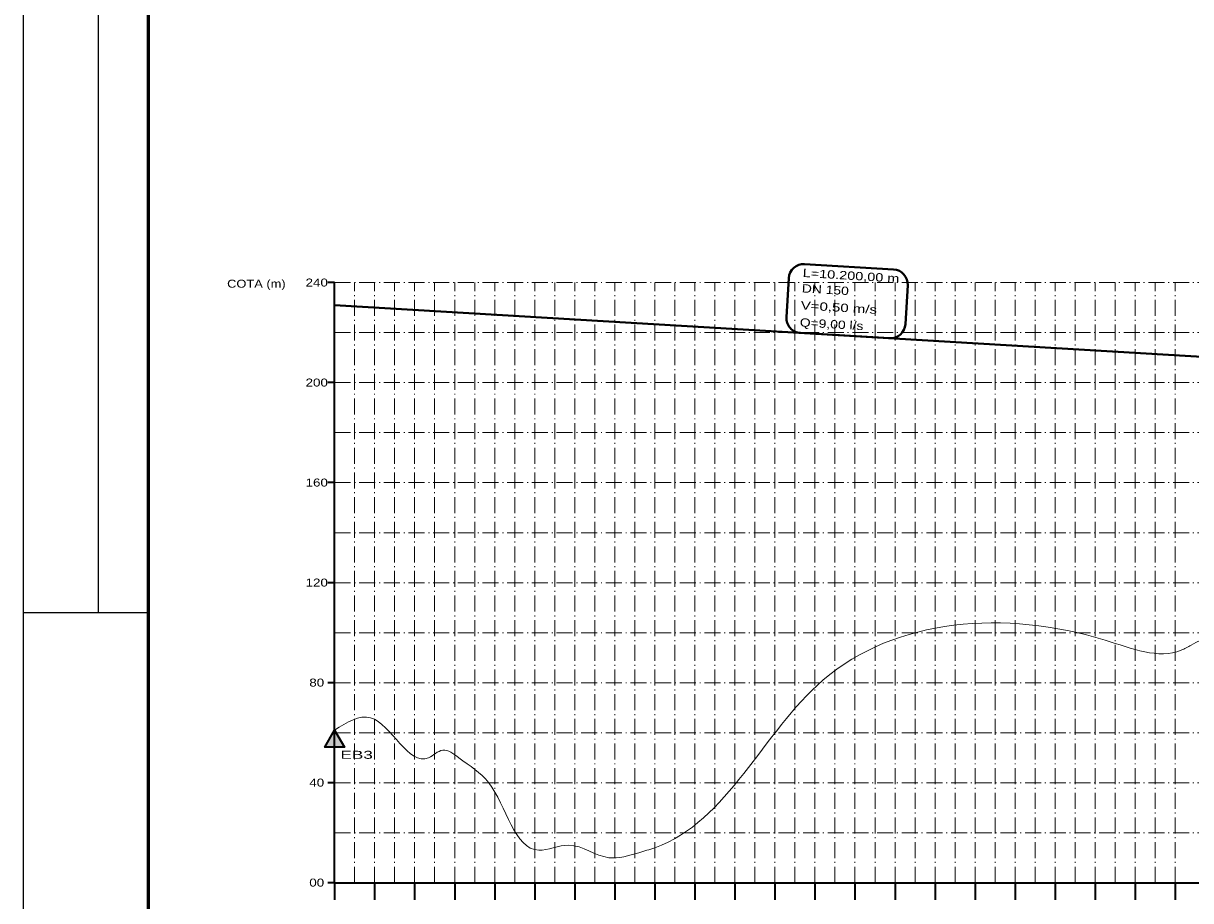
# Model space of a CAD drawing. Extents: x -4 to 42046, y -3 to 29697.
# Drawn here: x -4 to 11660, y 11967 to 20739 of the extents above; entities that cross this region are included whole.
import ezdxf
from ezdxf.enums import TextEntityAlignment as Align

# ---------------------------------------------------------------- set-up
doc = ezdxf.new("R2010")
doc.units = 0
doc.header["$LTSCALE"] = 32
doc.linetypes.add('DOT_DASHED', pattern=[7.7, 5, -1.2, 0.3, -1.2])
for name, color, linetype, lineweight in [('1', 7, 'DOT_DASHED', 13), ('24', 7, 'Continuous', 35), ('55', 7, 'Continuous', 13), ('62', 7, 'Continuous', 13), ('63', 7, 'Continuous', 25), ('9', 7, 'Continuous', 40)]:
    doc.layers.add(name, color=color, linetype=linetype, lineweight=lineweight)

msp = doc.modelspace()

# ---------------------------------------------------------------- hatches: boundary and pattern name
at = {"layer": '62'}
msp.add_hatch(color=256, dxfattribs=at).paths.add_polyline_path([(3105.77, 13671.17), (3204.42, 13502.71), (3009.21, 13501.5)])

# ---------------------------------------------------------------- linework, layer by layer
at = {"layer": '1'}
for p, q in [((3105.77, 18146.17), (22505.77, 18146.17)), ((3305.77, 12146.17), (3305.77, 18146.17)), ((3505.77, 12146.17), (3505.77, 18146.17)), ((3705.77, 12146.17), (3705.77, 18146.17)), ((3905.77, 12146.17), (3905.77, 18146.17)), ((4105.77, 12146.17), (4105.77, 18146.17)), ((4305.77, 12146.17), (4305.77, 18146.17)), ((4505.77, 12146.17), (4505.77, 18146.17)), ((4705.77, 12146.17), (4705.77, 18146.17)), ((4905.77, 12146.17), (4905.77, 18146.17)), ((5105.77, 12146.17), (5105.77, 18146.17)), ((5305.77, 12146.17), (5305.77, 18146.17)), ((5505.77, 12146.17), (5505.77, 18146.17)), ((5705.77, 12146.17), (5705.77, 18146.17)), ((5905.77, 12146.17), (5905.77, 18146.17)), ((6105.77, 12146.17), (6105.77, 18146.17)), ((6305.77, 12146.17), (6305.77, 18146.17)), ((6505.77, 12146.17), (6505.77, 18146.17)), ((6705.77, 12146.17), (6705.77, 18146.17)), ((6905.77, 12146.17), (6905.77, 18146.17)), ((7105.77, 12146.17), (7105.77, 18146.17)), ((7305.77, 12146.17), (7305.77, 18146.17)), ((7505.77, 12146.17), (7505.77, 18146.17)), ((7705.77, 12146.17), (7705.77, 18146.17)), ((7905.77, 12146.17), (7905.77, 18146.17)), ((8105.77, 12146.17), (8105.77, 18146.17)), ((8305.77, 12146.17), (8305.77, 18146.17)), ((8505.77, 12146.17), (8505.77, 18146.17)), ((8705.77, 12146.17), (8705.77, 18146.17)), ((8905.77, 12146.17), (8905.77, 18146.17)), ((9105.77, 12146.17), (9105.77, 18146.17)), ((9305.77, 12146.17), (9305.77, 18146.17)), ((9505.77, 12146.17), (9505.77, 18146.17)), ((9705.77, 12146.17), (9705.77, 18146.17)), ((9905.77, 12146.17), (9905.77, 18146.17)), ((10105.77, 12146.17), (10105.77, 18146.17)), ((10305.77, 12146.17), (10305.77, 18146.17)), ((10505.77, 12146.17), (10505.77, 18146.17)), ((10705.77, 12146.17), (10705.77, 18146.17)), ((10905.77, 12146.17), (10905.77, 18146.17)), ((11105.77, 12146.17), (11105.77, 18146.17)), ((11305.77, 12146.17), (11305.77, 18146.17)), ((11505.77, 12146.17), (11505.77, 18146.17)), ((3105.77, 17646.17), (22505.77, 17646.17)), ((3105.77, 17146.17), (22505.77, 17146.17)), ((3105.77, 16646.17), (22505.77, 16646.17)), ((3105.77, 16146.17), (22505.77, 16146.17)), ((3105.77, 15646.17), (22505.77, 15646.17)), ((3105.77, 15146.17), (22505.77, 15146.17)), ((3105.77, 14646.17), (22505.77, 14646.17)), ((3105.77, 14146.17), (22505.77, 14146.17)), ((3105.77, 13646.17), (22505.77, 13646.17)), ((3105.77, 13146.17), (22505.77, 13146.17)), ((3105.77, 12646.17), (22505.77, 12646.17))]:
    msp.add_line(p, q, dxfattribs=at)
at = {"layer": '55'}
msp.add_spline([(3105.77, 13671.17), (3465.77, 13796.17), (4045.77, 13396.17), (4185.77, 13471.17), (4345.77, 13396.17), (4645.77, 13146.17), (5145.77, 12471.17), (5445.77, 12521.17), (5845.77, 12396.17), (6145.77, 12446.17), (6305.77, 12496.17), (7985.77, 14171.17), (10805.77, 14571.17), (11565.77, 14471.17), (11665.77, 14521.17), (12465.77, 14721.17), (12585.77, 14646.17), (12705.77, 14521.17), (12945.77, 14646.17), (13165.77, 14696.17), (13305.77, 14646.17), (13765.77, 14646.17), (15305.77, 14896.17), (15505.77, 14971.17), (15705.77, 14896.17), (16705.77, 13396.17), (17105.77, 13396.17), (17405.77, 13771.17), (17705.77, 13771.17), (17905.77, 13471.17), (18505.77, 14971.17), (18685.77, 14646.17), (19185.77, 14996.17), (19665.77, 14396.17), (19865.77, 15071.17), (20065.77, 14646.17), (20265.77, 15124.39), (21005.77, 13396.17), (21325.77, 12896.17), (21625.77, 13396.17), (22005.77, 13146.17), (22505.77, 13646.17)], degree=3, dxfattribs=at)
at = {"layer": '62', "lineweight": 35}
for p, q in [((3105.77, 18146.17), (3037.5, 18146.17)), ((3101.57, 18146.17), (3105.77, 18146.17)), ((3105.77, 12146.17), (3105.77, 18146.17)), ((3101.57, 17896.17), (3105.77, 17896.17)), ((3101.57, 17646.17), (3105.77, 17646.17)), ((3101.57, 17396.17), (3105.77, 17396.17)), ((3105.77, 17146.17), (3037.5, 17146.17)), ((3101.57, 17146.17), (3105.77, 17146.17)), ((3101.57, 16896.17), (3105.77, 16896.17)), ((3101.57, 16646.17), (3105.77, 16646.17)), ((3101.57, 16396.17), (3105.77, 16396.17)), ((3105.77, 16146.17), (3037.5, 16146.17)), ((3101.57, 16146.17), (3105.77, 16146.17)), ((3101.57, 15896.17), (3105.77, 15896.17)), ((3101.57, 15646.17), (3105.77, 15646.17)), ((3101.57, 15396.17), (3105.77, 15396.17)), ((3105.77, 15146.17), (3037.5, 15146.17)), ((3101.57, 15146.17), (3105.77, 15146.17)), ((3101.57, 14896.17), (3105.77, 14896.17)), ((3101.57, 14646.17), (3105.77, 14646.17)), ((3101.57, 14396.17), (3105.77, 14396.17)), ((3105.77, 14146.17), (3037.5, 14146.17)), ((3101.57, 14146.17), (3105.77, 14146.17)), ((3101.57, 13896.17), (3105.77, 13896.17)), ((3101.57, 13646.17), (3105.77, 13646.17)), ((3101.57, 13396.17), (3105.77, 13396.17)), ((3101.57, 13146.17), (3105.77, 13146.17)), ((3101.57, 12896.17), (3105.77, 12896.17)), ((3101.57, 12646.17), (3105.77, 12646.17)), ((3101.57, 12396.17), (3105.77, 12396.17)), ((3105.77, 12146.17), (3037.5, 12146.17)), ((3105.77, 12146.17), (3105.77, 11975.48)), ((3105.77, 12146.17), (22505.77, 12146.17)), ((3505.77, 12146.17), (3505.77, 11975.48)), ((3905.77, 12146.17), (3905.77, 11975.48)), ((4305.77, 12146.17), (4305.77, 11975.48)), ((4705.77, 12146.17), (4705.77, 11975.48)), ((5105.77, 12146.17), (5105.77, 11975.48)), ((5505.77, 12146.17), (5505.77, 11975.48)), ((5905.77, 12146.17), (5905.77, 11975.48)), ((6305.77, 12146.17), (6305.77, 11975.48)), ((6705.77, 12146.17), (6705.77, 11975.48)), ((7105.77, 12146.17), (7105.77, 11975.48)), ((7505.77, 12146.17), (7505.77, 11975.48)), ((7905.77, 12146.17), (7905.77, 11975.48)), ((8305.77, 12146.17), (8305.77, 11975.48)), ((8705.77, 12146.17), (8705.77, 11975.48)), ((9105.77, 12146.17), (9105.77, 11975.48)), ((9505.77, 12146.17), (9505.77, 11975.48)), ((9905.77, 12146.17), (9905.77, 11975.48)), ((10305.77, 12146.17), (10305.77, 11975.48)), ((10705.77, 12146.17), (10705.77, 11975.48)), ((11105.77, 12146.17), (11105.77, 11975.48)), ((11505.77, 12146.17), (11505.77, 11975.48))]:
    msp.add_line(p, q, dxfattribs=at)
at = {"layer": '62'}
for p, q in [((3101.57, 18096.17), (3105.77, 18096.17)), ((3101.57, 18046.17), (3105.77, 18046.17)), ((3101.57, 17996.17), (3105.77, 17996.17)), ((3101.57, 17946.17), (3105.77, 17946.17)), ((3101.57, 17846.17), (3105.77, 17846.17)), ((3101.57, 17796.17), (3105.77, 17796.17)), ((3101.57, 17746.17), (3105.77, 17746.17)), ((3101.57, 17696.17), (3105.77, 17696.17)), ((3101.57, 17596.17), (3105.77, 17596.17)), ((3101.57, 17546.17), (3105.77, 17546.17)), ((3101.57, 17496.17), (3105.77, 17496.17)), ((3101.57, 17446.17), (3105.77, 17446.17)), ((3101.57, 17346.17), (3105.77, 17346.17)), ((3101.57, 17296.17), (3105.77, 17296.17)), ((3101.57, 17246.17), (3105.77, 17246.17)), ((3101.57, 17196.17), (3105.77, 17196.17)), ((3101.57, 17096.17), (3105.77, 17096.17)), ((3101.57, 17046.17), (3105.77, 17046.17)), ((3101.57, 16996.17), (3105.77, 16996.17)), ((3101.57, 16946.17), (3105.77, 16946.17)), ((3101.57, 16846.17), (3105.77, 16846.17)), ((3101.57, 16796.17), (3105.77, 16796.17)), ((3101.57, 16746.17), (3105.77, 16746.17)), ((3101.57, 16696.17), (3105.77, 16696.17)), ((3101.57, 16596.17), (3105.77, 16596.17)), ((3101.57, 16546.17), (3105.77, 16546.17)), ((3101.57, 16496.17), (3105.77, 16496.17)), ((3101.57, 16446.17), (3105.77, 16446.17)), ((3101.57, 16346.17), (3105.77, 16346.17)), ((3101.57, 16296.17), (3105.77, 16296.17)), ((3101.57, 16246.17), (3105.77, 16246.17)), ((3101.57, 16196.17), (3105.77, 16196.17)), ((3101.57, 16096.17), (3105.77, 16096.17)), ((3101.57, 16046.17), (3105.77, 16046.17)), ((3101.57, 15996.17), (3105.77, 15996.17)), ((3101.57, 15946.17), (3105.77, 15946.17)), ((3101.57, 15846.17), (3105.77, 15846.17)), ((3101.57, 15796.17), (3105.77, 15796.17)), ((3101.57, 15746.17), (3105.77, 15746.17)), ((3101.57, 15696.17), (3105.77, 15696.17)), ((3101.57, 15596.17), (3105.77, 15596.17)), ((3101.57, 15546.17), (3105.77, 15546.17)), ((3101.57, 15496.17), (3105.77, 15496.17)), ((3101.57, 15446.17), (3105.77, 15446.17)), ((3101.57, 15346.17), (3105.77, 15346.17)), ((3101.57, 15296.17), (3105.77, 15296.17)), ((3101.57, 15246.17), (3105.77, 15246.17)), ((3101.57, 15196.17), (3105.77, 15196.17)), ((3101.57, 15096.17), (3105.77, 15096.17)), ((3101.57, 15046.17), (3105.77, 15046.17)), ((3101.57, 14996.17), (3105.77, 14996.17)), ((3101.57, 14946.17), (3105.77, 14946.17)), ((3101.57, 14846.17), (3105.77, 14846.17)), ((3101.57, 14796.17), (3105.77, 14796.17)), ((3101.57, 14746.17), (3105.77, 14746.17)), ((3101.57, 14696.17), (3105.77, 14696.17)), ((3101.57, 14596.17), (3105.77, 14596.17)), ((3101.57, 14546.17), (3105.77, 14546.17)), ((3101.57, 14496.17), (3105.77, 14496.17)), ((3101.57, 14446.17), (3105.77, 14446.17)), ((3101.57, 14346.17), (3105.77, 14346.17)), ((3101.57, 14296.17), (3105.77, 14296.17)), ((3101.57, 14246.17), (3105.77, 14246.17)), ((3101.57, 14196.17), (3105.77, 14196.17)), ((3101.57, 14096.17), (3105.77, 14096.17)), ((3101.57, 14046.17), (3105.77, 14046.17)), ((3101.57, 13996.17), (3105.77, 13996.17)), ((3101.57, 13946.17), (3105.77, 13946.17)), ((3101.57, 13846.17), (3105.77, 13846.17)), ((3101.57, 13796.17), (3105.77, 13796.17)), ((3101.57, 13746.17), (3105.77, 13746.17)), ((3101.57, 13696.17), (3105.77, 13696.17)), ((3101.57, 13596.17), (3105.77, 13596.17)), ((3101.57, 13546.17), (3105.77, 13546.17)), ((3101.57, 13496.17), (3105.77, 13496.17)), ((3101.57, 13446.17), (3105.77, 13446.17)), ((3101.57, 13346.17), (3105.77, 13346.17)), ((3101.57, 13296.17), (3105.77, 13296.17)), ((3101.57, 13246.17), (3105.77, 13246.17)), ((3101.57, 13196.17), (3105.77, 13196.17)), ((3101.57, 13096.17), (3105.77, 13096.17)), ((3101.57, 13046.17), (3105.77, 13046.17)), ((3101.57, 12996.17), (3105.77, 12996.17)), ((3101.57, 12946.17), (3105.77, 12946.17)), ((3101.57, 12846.17), (3105.77, 12846.17)), ((3101.57, 12796.17), (3105.77, 12796.17)), ((3101.57, 12746.17), (3105.77, 12746.17)), ((3101.57, 12696.17), (3105.77, 12696.17)), ((3101.57, 12596.17), (3105.77, 12596.17)), ((3101.57, 12546.17), (3105.77, 12546.17)), ((3101.57, 12496.17), (3105.77, 12496.17)), ((3101.57, 12446.17), (3105.77, 12446.17)), ((3101.57, 12346.17), (3105.77, 12346.17)), ((3101.57, 12296.17), (3105.77, 12296.17)), ((3101.57, 12246.17), (3105.77, 12246.17)), ((3101.57, 12196.17), (3105.77, 12196.17))]:
    msp.add_line(p, q, dxfattribs=at)
at = {"layer": '62', "lineweight": 35}
msp.add_lwpolyline([(3105.77, 13671.17), (3204.42, 13502.71), (3009.21, 13501.5)], close=True, dxfattribs=at)
msp.add_lwpolyline([(3101.57, 13146.17), (3105.77, 13146.17), (3037.5, 13146.17)], dxfattribs=at)
at = {"layer": '63'}
for p, q in [((-4.21, -2.97), (-4.21, 29697.03)), ((745.8, 14847.03), (745.8, 29697.03)), ((-4.21, 14847.03), (1245.8, 14847.03))]:
    msp.add_line(p, q, dxfattribs=at)
at = {"layer": '63', "lineweight": 60}
msp.add_lwpolyline([(23554.57, 497.03), (1245.8, 497.03), (1245.8, 29197.03)], dxfattribs=at)
at = {"layer": '9'}
for p, q in [((7802.33, 18331.79), (8691.59, 18278.63)), ((7643.65, 18191), (7620.36, 17801.44)), ((8832.37, 18119.94), (8809.09, 17730.38)), ((13305.77, 17311.3), (3105.77, 17921.05)), ((7761.14, 17642.75), (8650.4, 17589.59))]:
    msp.add_line(p, q, dxfattribs=at)
for centre, start, end in [((7793.38, 18182.05), 86.57896, 176.57896), ((8682.64, 18128.89), 356.57896, 86.57896), ((7770.09, 17792.49), 176.57896, 266.57896), ((8659.35, 17739.33), 266.57896, 356.57896)]:
    msp.add_arc(centre, 150, start, end, dxfattribs=at)

# ---------------------------------------------------------------- texts
at = {"layer": '24', "width": 1.2}
msp.add_text('COTA (m)', height=80, dxfattribs=at).set_placement((2616.74, 18095.49), align=Align.RIGHT)
at = {"layer": '24', "width": 1.25}
for s, p in [('240', (2927.38, 18107.23)), ('200', (2927.38, 17107.23)), ('160', (2927.38, 16107.23)), ('120', (2927.38, 15107.23)), ('80', (2927.38, 14107.23)), ('40', (2927.38, 13107.23)), ('00', (2927.38, 12107.23))]:
    msp.add_text(s, height=80, dxfattribs=at).set_placement(p, align=Align.CENTER)
at = {"layer": '24', "width": 1.6}
msp.add_text('EB3', height=80, dxfattribs=at).set_placement((3164.46, 13385))
at = {"layer": '9'}
for s, width, p in [('L=10.200,00 m', 1.3, (7781.75, 18203.32)), ('DN 150', 1.25, (7772.53, 18049.1)), ('V=0,50 m/s', 1.35, (7762.35, 17878.82)), ('Q=9,00 l/s', 1.25, (7752.17, 17708.53))]:
    msp.add_text(s, height=82.98, rotation=356.579, dxfattribs=dict(at, width=width)).set_placement(p)

doc.saveas('drawing.dxf')
